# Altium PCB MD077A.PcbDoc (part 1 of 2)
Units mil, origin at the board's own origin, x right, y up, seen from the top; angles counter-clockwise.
Board outline 2838.2 x 1916.85 mil, 4 copper layers (Top Layer, Signal Layer 1, Signal Layer 2, Bottom Layer), stack 61.2 mil thick; 81 components, 30 nets, 187 pads, 201 vias.
Unrouted connection lines stored in the file: 7.
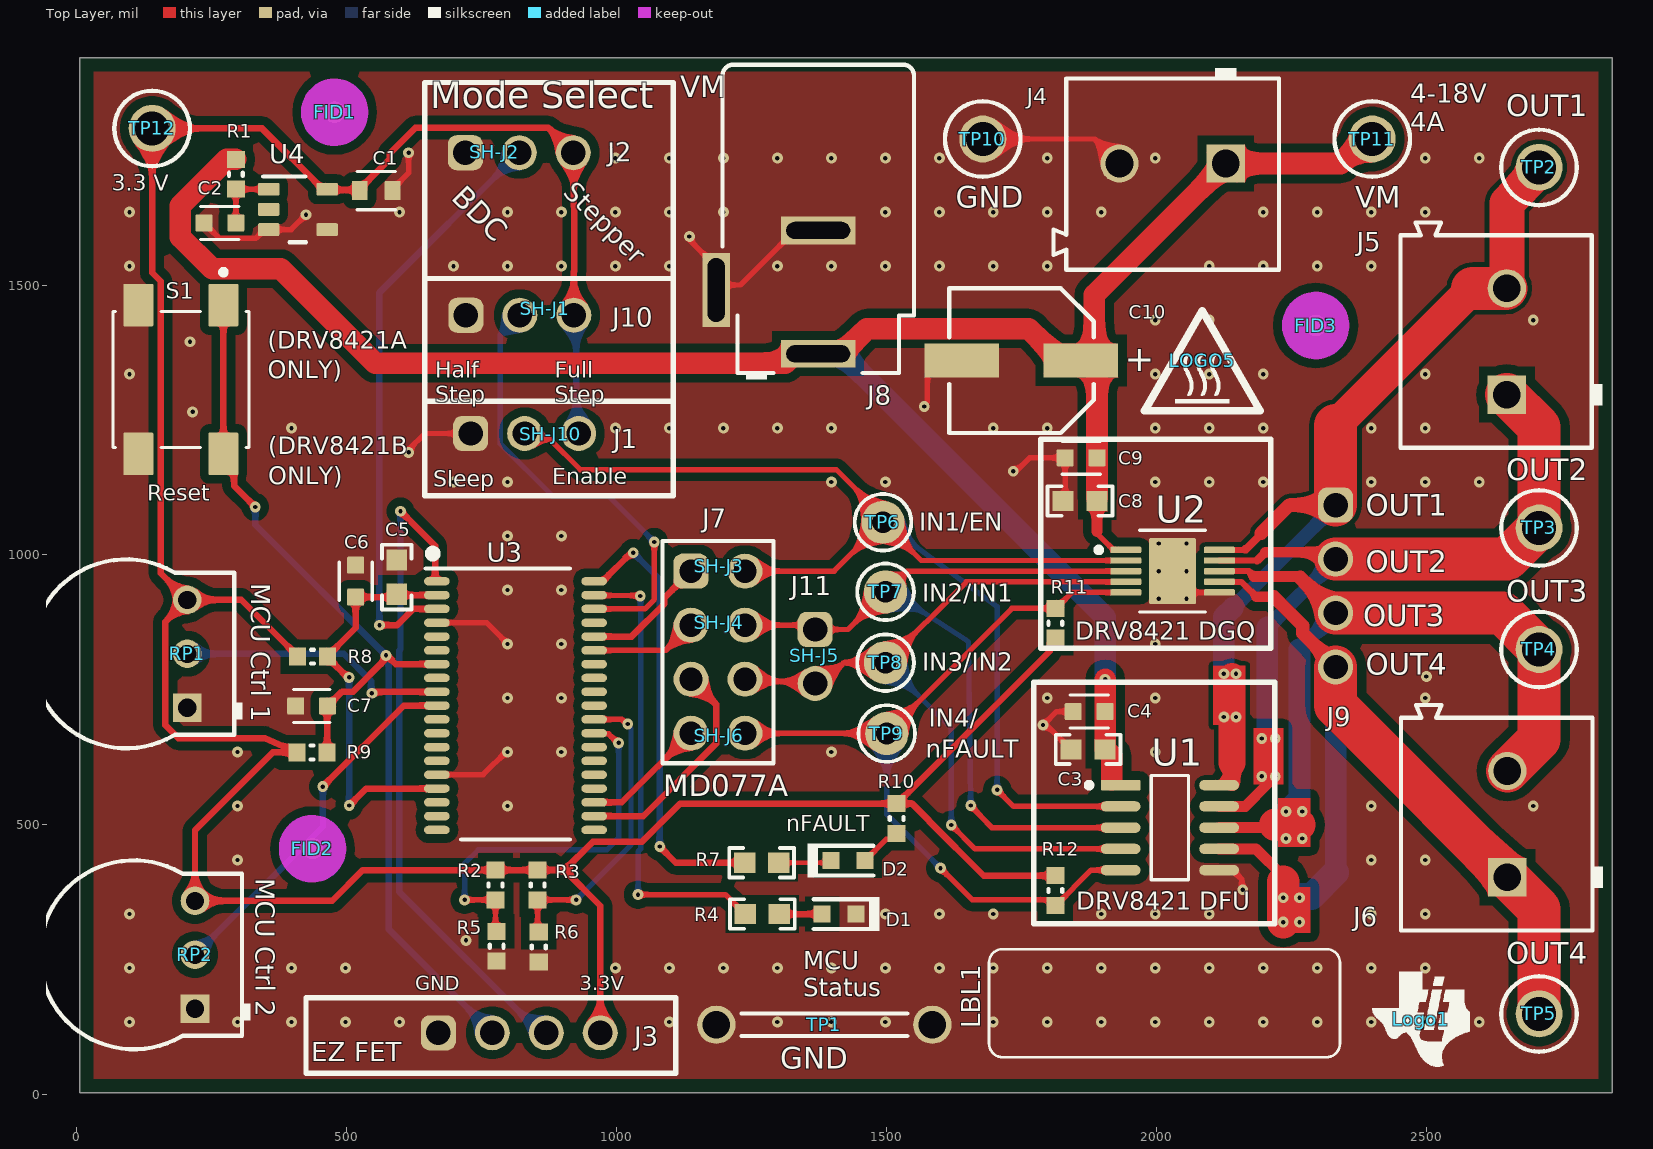
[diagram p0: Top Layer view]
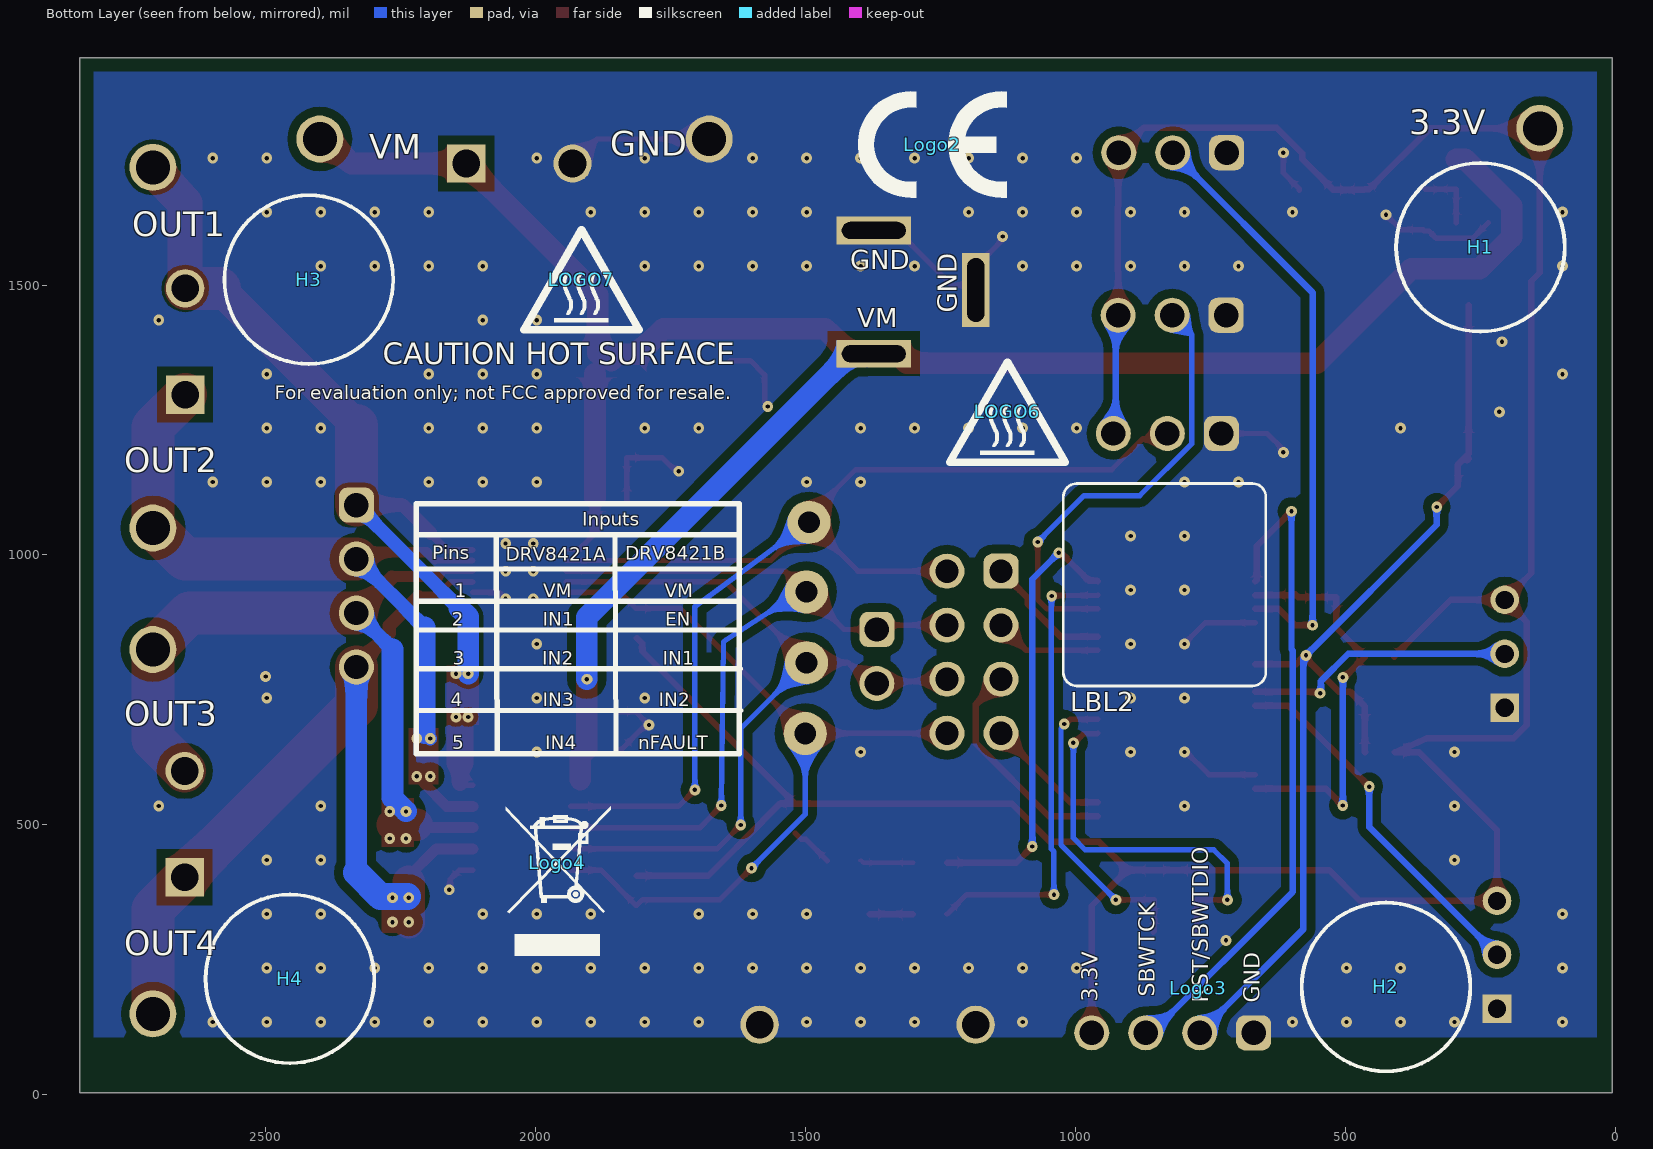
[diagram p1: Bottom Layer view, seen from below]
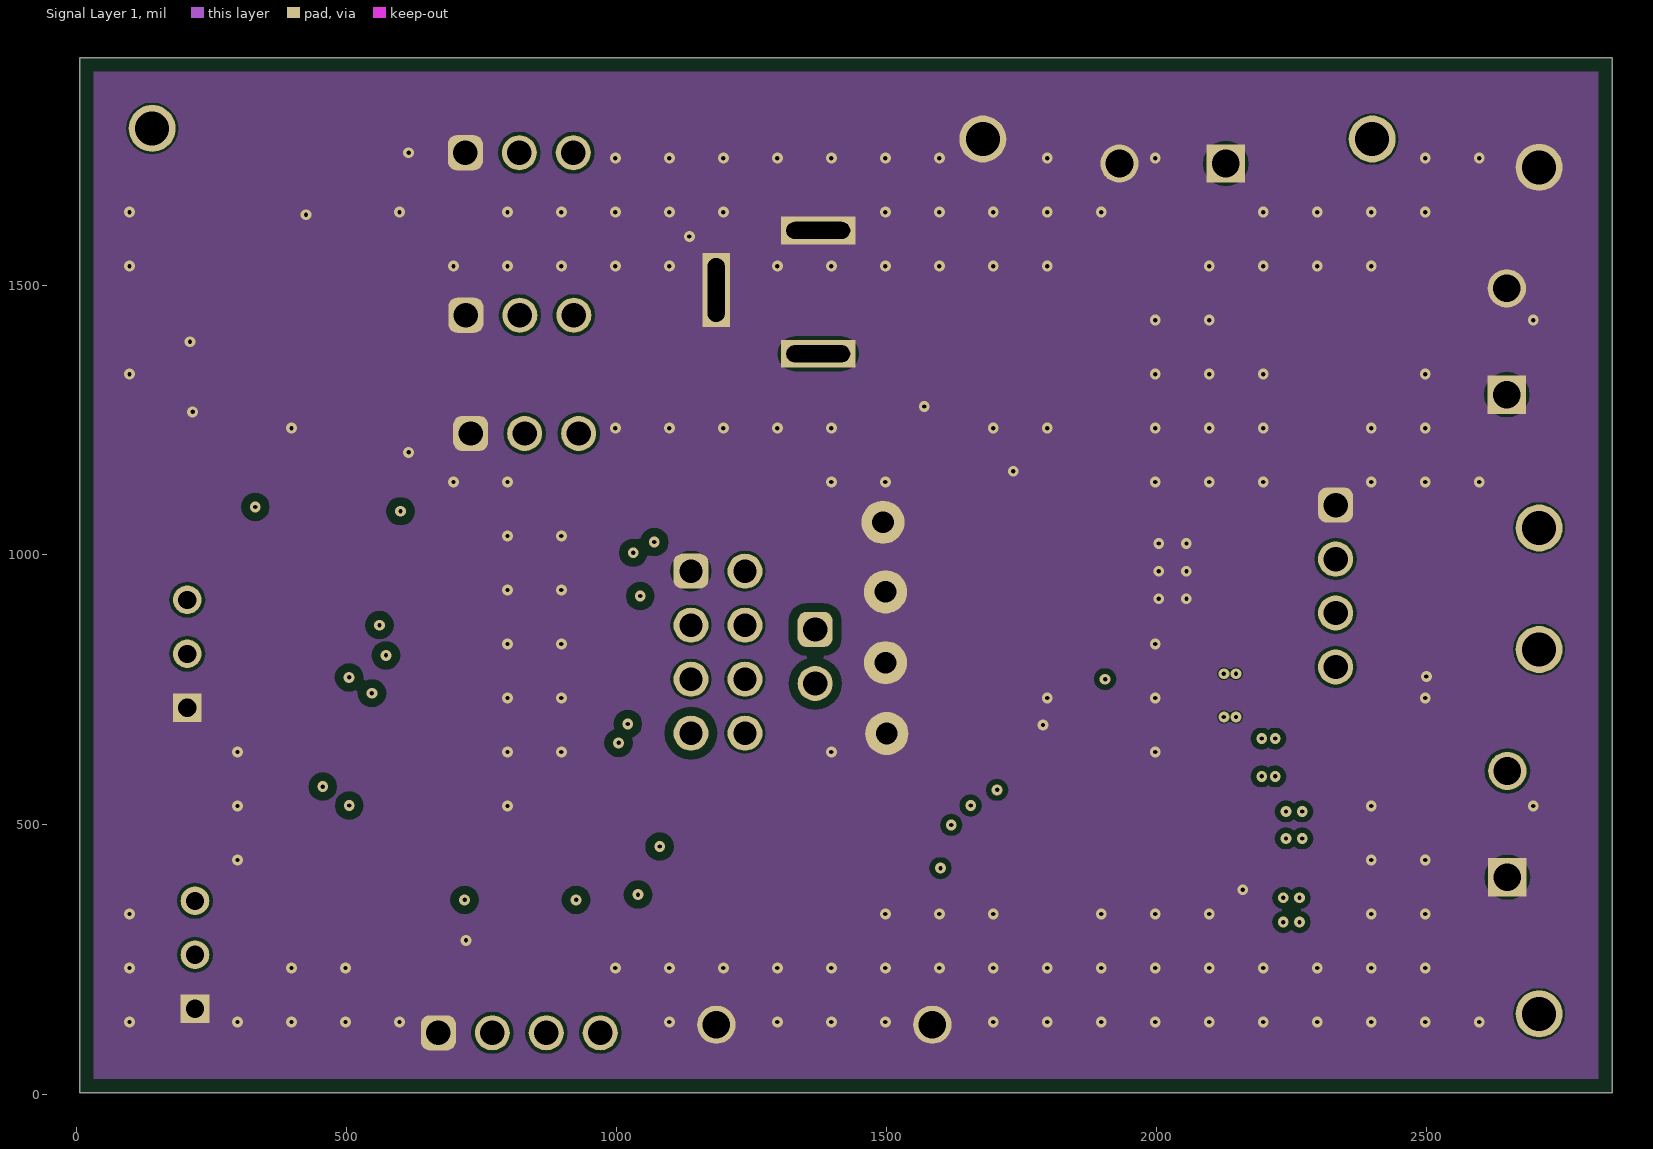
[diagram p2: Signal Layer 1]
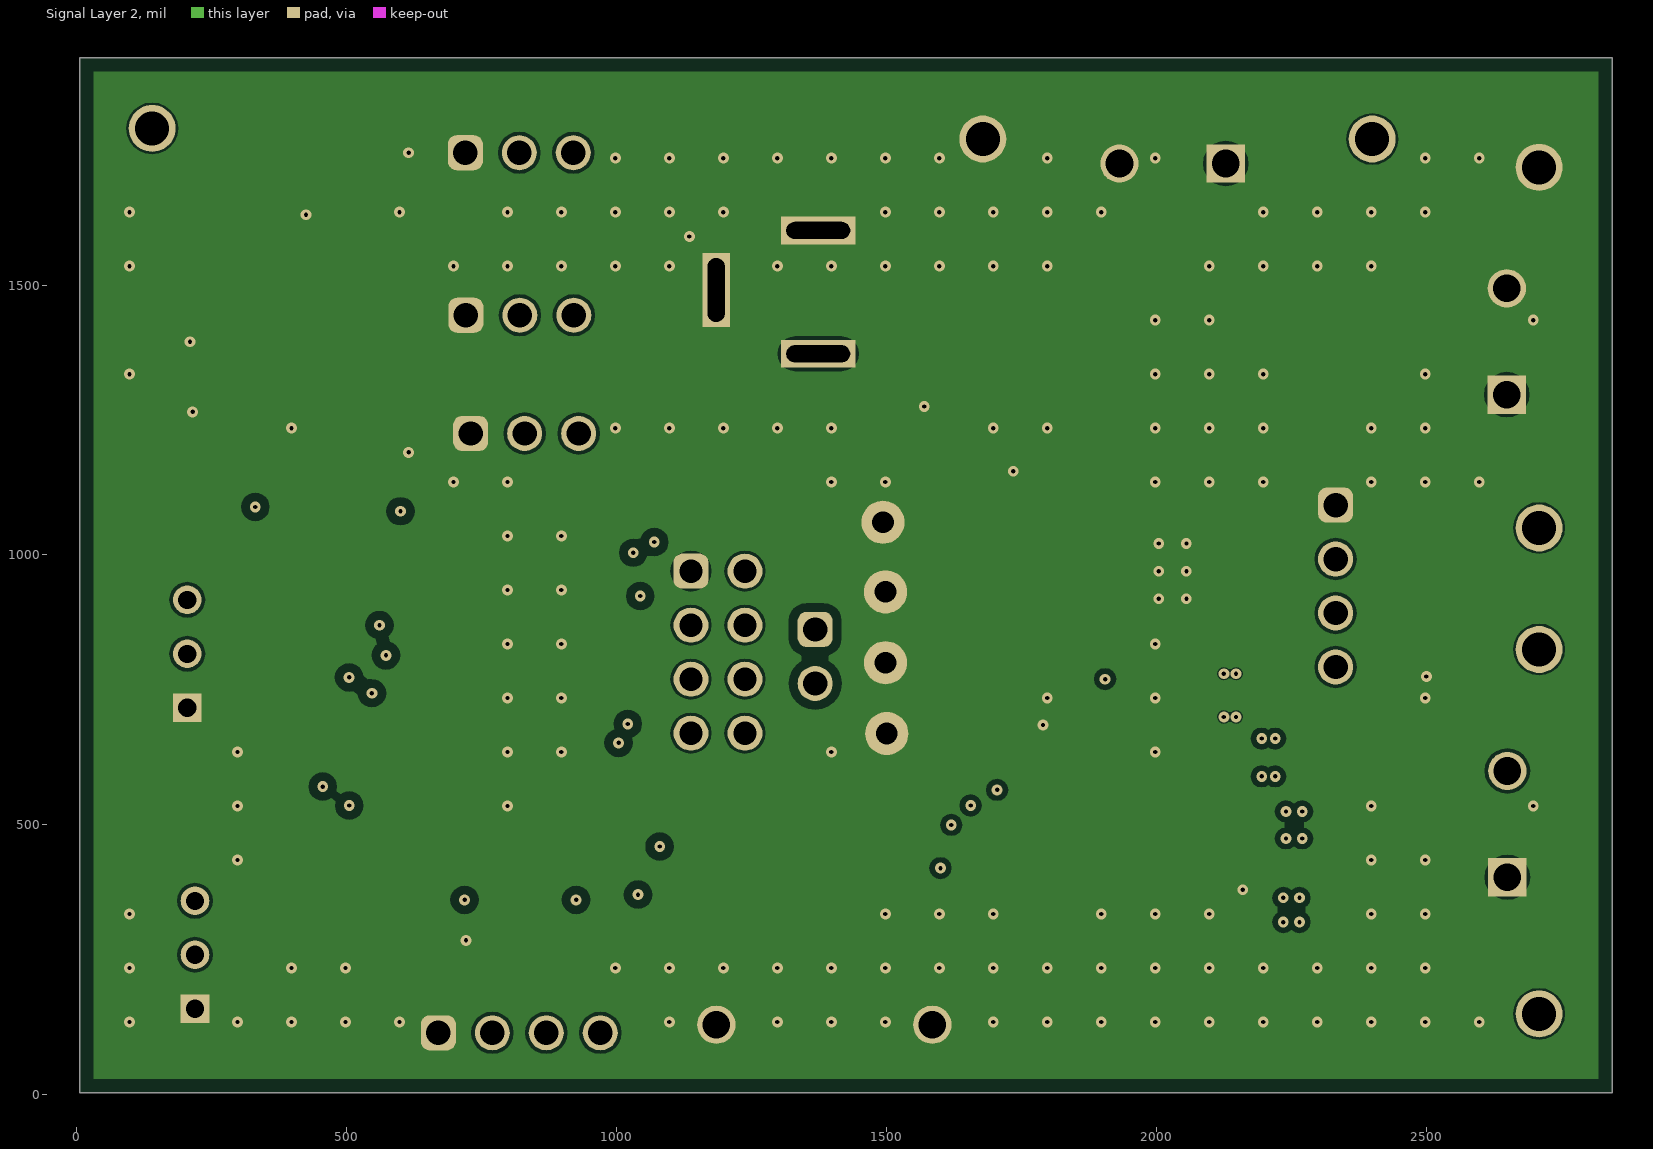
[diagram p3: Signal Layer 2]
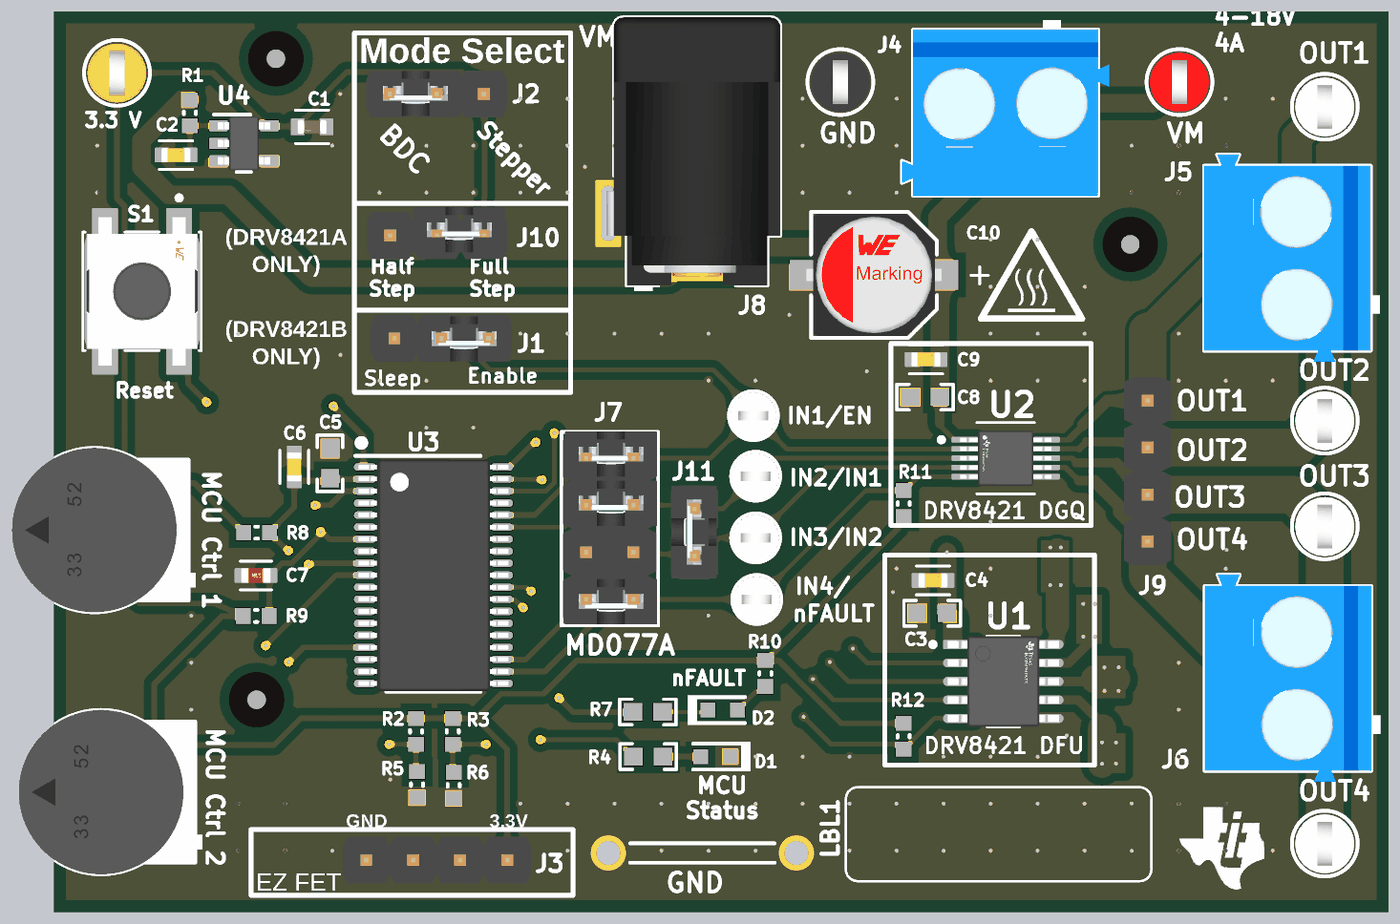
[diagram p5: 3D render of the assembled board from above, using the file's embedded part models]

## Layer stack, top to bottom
Top Solder: solder mask 0.4, Solder Resist, Dk 3.5
Top Layer: signal copper 2.8
Dielectric 1: prepreg 11.4, FR4 370, Dk 4.2
Signal Layer 1: signal copper 1.4
Dielectric 2: core 30, FR4 370, Dk 4.2
Signal Layer 2: signal copper 1.4
Dielectric 3: prepreg 11.4, FR4 370, Dk 4.2
Bottom Layer: signal copper 2.8
Bottom Solder: solder mask 0.4, Solder Resist, Dk 3.5

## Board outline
6,1920.85 6,4 2844.2,4 2844.2,1920.85

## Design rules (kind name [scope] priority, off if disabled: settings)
AcuteAngle [All] p1: minimum=4.50000000000000E+0001 checktracksonly=FALSE
AssemblyTestPointUsage [All] p1: valid=2
BoardOutlineClearance BoardOutlineClearance_MountingHoles [OnCopper and InComponentClass('Mounting Holes')] p1: gap=39.37 ignorepadtopadclearanceinfootprint=FALSE
BoardOutlineClearance BoardOutlineClearance_Poly [OnCopper and IsPoly] p2: gap=25 ignorepadtopadclearanceinfootprint=FALSE
BoardOutlineClearance BoardOutlineClearance_Region [OnCopper and IsRegion] p3: gap=25 ignorepadtopadclearanceinfootprint=FALSE
BoardOutlineClearance [OnCopper and Not InComponentClass('Logo') and not InComponentClass('FiducialMark') and not InRegion(1000,500,4000,800) and not InPoly] p4: gap=75 ignorepadtopadclearanceinfootprint=FALSE
Clearance Clearance_18 [InNet('OUT1')] p1: gap=8 ignorepadtopadclearanceinfootprint=TRUE
Clearance Clearance_Keepouts [((IsTrack Or IsArc) And Not InPoly) And IsFree and IsKeepOut vs ((IsTrack Or IsArc) And Not InPoly) And IsFree and IsKeepOut] p2: gap=0 ignorepadtopadclearanceinfootprint=FALSE
Clearance Clearance_Poly [InPolygon] p3: gap=16 ignorepadtopadclearanceinfootprint=TRUE
Clearance Clearance_FiducialMark [IsKeepOut and InComponentClass('FiducialMark') vs IsPad and InComponentClass('FiducialMark')] p4: gap=0 ignorepadtopadclearanceinfootprint=FALSE
Clearance [All] p5: gap=7.87 ignorepadtopadclearanceinfootprint=TRUE
ComponentClearance ComponentClearance_MountingHoles_FiducialMarks [InComponentClass('Mounting Holes') vs InComponentClass('FiducialMark')] p1: gap=50 collisioncheckmode=3 verticalgap=10 showdistances=FALSE
ComponentClearance ComponentClearance_Shunt [InComponentClass('Shunt')] p2: gap=0 collisioncheckmode=3 verticalgap=0 showdistances=FALSE
ComponentClearance ComponentClearance_Logo [InComponentClass('Logo')] p3: gap=50 collisioncheckmode=3 verticalgap=10 showdistances=FALSE
ComponentClearance ComponentClearance_ScrewToNut [(HasFootprint('NY PMS 440 0025 PH')) vs (HasFootprint('Keystone_1902C'))] p4: gap=5 collisioncheckmode=3 verticalgap=10 showdistances=FALSE
ComponentClearance ComponentClearance_MountingHoles [InComponentClass('Mounting Holes')] p5: gap=250 collisioncheckmode=3 verticalgap=100000 showdistances=FALSE
ComponentClearance ComponentClearance_SmallPassives [HasFootprint('0201*') or HasFootprint('0402*') or HasFootprint('0508') or HasFootprint('0603*') or HasFootprint('0612') or HasFootprint('0805*') or HasFootprint('0815*') or HasFootprint('0830*') or HasFootprint('1206*') or HasFootprint('1210*') or HasFootprint('1808*') or HasFootprint('1812*') or HasFootprint('1825*') or HasFootprint('2010*') or HasFootprint('2220*') or HasFootprint('2225*') or HasFootprint('2512*') or HasFootprint('2728*') or HasFootprint('3518*') vs HasFootprint('0201*') or HasFootprint('0402*') or HasFootprint('0508') or HasFootprint('0603*') or HasFootprint('0612') or HasFootprint('0805*') or HasFootprint('0815*') or HasFootprint('0830*') or HasFootprint('1206*') or HasFootprint('1210*') or HasFootprint('1808*') or HasFootprint('1812*') or HasFootprint('1825*') or HasFootprint('2010*') or HasFootprint('2220*') or HasFootprint('2225*') or HasFootprint('2512*') or HasFootprint('2728*') or HasFootprint('3518*')] p6: gap=14.96 collisioncheckmode=3 verticalgap=10 showdistances=FALSE
ComponentClearance ComponentClearance_THtoSMT [IsThruComponent vs IsSMTComponent] p7: gap=40 collisioncheckmode=3 verticalgap=30 showdistances=FALSE
ComponentClearance ComponentClearance_THtoTH [IsThruComponent vs IsThruComponent] p8: gap=30 collisioncheckmode=3 verticalgap=30 showdistances=FALSE
ComponentClearance [All] p9: gap=30 collisioncheckmode=3 verticalgap=10 showdistances=FALSE
DiffPairsRouting [All] p1: maxlimit=100 minlimit=10 mostfreqgap=10 toplayer_minwidth=6.3 toplayer_maxwidth=15 toplayer_prefwidth=10 midlayer1_minwidth=15 midlayer1_maxwidth=15 midlayer1_prefwidth=15 midlayer2_minwidth=15 midlayer2_maxwidth=15 midlayer2_prefwidth=15 bottomlayer_minwidth=6.3 bottomlayer_maxwidth=15 bottomlayer_prefwidth=10 maxuncoupledlength=1000
FabricationTestPointUsage TestPointUsage [All] p1: valid=2 allowmultiple=FALSE
FabricationTestpoint Testpoint [All] p1: side=3 testpointundercomponent=TRUE minsize=40 maxsize=100 preferedsize=60 minholesize=0 maxholesize=40 preferedholesize=32 testpointgrid=1 allowsidetop=TRUE allowsidebottom=TRUE usegrid=TRUE gridtolerance=0.01
FanoutControl Fanout_LCC [IsLCC] p1: bgadir=Out bgaviamode=Centered fanoutstyle=Auto fanoutdirection=Alternating viagrid=1 // Fanout_LCC (Default Rule)
FanoutControl Fanout_BGA [IsBGA] p2: bgadir=Out bgaviamode=Centered fanoutstyle=Auto fanoutdirection=Alternating viagrid=1 // Fanout_BGA (Default Rule)
FanoutControl Fanout_Default [All] p4: bgadir=Out bgaviamode=Centered fanoutstyle=Auto fanoutdirection=Alternating viagrid=1 // Fanout_Default (Default Rule)
FanoutControl Fanout_Small [(CompPinCount < 5)] p5: bgadir=Out bgaviamode=Centered fanoutstyle=Auto fanoutdirection=OutThenIn viagrid=1 // Fanout_Small (Default Rule)
HoleSize [All] p1: absolutevalues=TRUE maxlimit=251 minlimit=7.87 maxpercent=80.000 minpercent=20.000
HoleToHoleClearance [All] p1: gap=12 allowstackedmicrovias=TRUE
MinimumAnnularRing MinimumAnnularRing_ThermalPadVias [IsVia and InAnyComponent] p1: minimumring=5.91
MinimumAnnularRing [All] p2: minimumring=7.87
MinimumSolderMaskSliver MinimumSolderMaskSliver_Logo [InComponentClass('Logo') vs InComponentClass('Logo')] p1: minsoldermaskwidth=0.7
MinimumSolderMaskSliver [All] p2: minsoldermaskwidth=3.94
PlaneConnect [All] p1: planeconnectstyle=Direct reliefexpansion=10 reliefentries=4 reliefconductorwidth=10 reliefairgap=10
PolygonConnect PolygonConnect_94 [All vs IsNamedPolygon('BOTTOM_LAYER_GND_P203')] p1: thpad.connectstyle=Direct thpad.reliefconductorwidth=10 thpad.reliefentries=4 thpad.polygonreliefangle="90 Angle" thpad.airgapwidth=10 smdpad.connectstyle=Direct smdpad.reliefconductorwidth=10 smdpad.reliefentries=4 smdpad.polygonreliefangle="90 Angle" smdpad.airgapwidth=10 via.connectstyle=Relief via.reliefconductorwidth=10 via.reliefentries=4 via.polygonreliefangle="90 Angle" via.airgapwidth=10
PolygonConnect PolygonConnect_93 [All vs IsNamedPolygon('SIGNAL_LAYER_2_EZFET_VBUS_P136')] p2: thpad.connectstyle=Direct thpad.reliefconductorwidth=10 thpad.reliefentries=4 thpad.polygonreliefangle="90 Angle" thpad.airgapwidth=10 smdpad.connectstyle=Direct smdpad.reliefconductorwidth=10 smdpad.reliefentries=4 smdpad.polygonreliefangle="90 Angle" smdpad.airgapwidth=10 via.connectstyle=Relief via.reliefconductorwidth=10 via.reliefentries=4 via.polygonreliefangle="90 Angle" via.airgapwidth=10
PolygonConnect PolygonConnect_92 [All vs IsNamedPolygon('TOP_LAYER_VM_P244')] p3: thpad.connectstyle=Direct thpad.reliefconductorwidth=10 thpad.reliefentries=4 thpad.polygonreliefangle="90 Angle" thpad.airgapwidth=10 smdpad.connectstyle=Direct smdpad.reliefconductorwidth=10 smdpad.reliefentries=4 smdpad.polygonreliefangle="90 Angle" smdpad.airgapwidth=10 via.connectstyle=Relief via.reliefconductorwidth=10 via.reliefentries=4 via.polygonreliefangle="90 Angle" via.airgapwidth=10
PolygonConnect PolygonConnect_91 [All vs IsNamedPolygon('TOP_LAYER_BOUT2_P242')] p4: thpad.connectstyle=Direct thpad.reliefconductorwidth=10 thpad.reliefentries=4 thpad.polygonreliefangle="90 Angle" thpad.airgapwidth=10 smdpad.connectstyle=Direct smdpad.reliefconductorwidth=10 smdpad.reliefentries=4 smdpad.polygonreliefangle="90 Angle" smdpad.airgapwidth=10 via.connectstyle=Relief via.reliefconductorwidth=10 via.reliefentries=4 via.polygonreliefangle="90 Angle" via.airgapwidth=10
PolygonConnect PolygonConnect_90 [All vs IsNamedPolygon('TOP_LAYER_VM_P239')] p5: thpad.connectstyle=Direct thpad.reliefconductorwidth=10 thpad.reliefentries=4 thpad.polygonreliefangle="90 Angle" thpad.airgapwidth=10 smdpad.connectstyle=Direct smdpad.reliefconductorwidth=10 smdpad.reliefentries=4 smdpad.polygonreliefangle="90 Angle" smdpad.airgapwidth=10 via.connectstyle=Relief via.reliefconductorwidth=10 via.reliefentries=4 via.polygonreliefangle="90 Angle" via.airgapwidth=10
PolygonConnect PolygonConnect_89 [All vs IsNamedPolygon('TOP_LAYER_BOUT1_P240')] p6: thpad.connectstyle=Direct thpad.reliefconductorwidth=10 thpad.reliefentries=4 thpad.polygonreliefangle="90 Angle" thpad.airgapwidth=10 smdpad.connectstyle=Direct smdpad.reliefconductorwidth=10 smdpad.reliefentries=4 smdpad.polygonreliefangle="90 Angle" smdpad.airgapwidth=10 via.connectstyle=Relief via.reliefconductorwidth=10 via.reliefentries=4 via.polygonreliefangle="90 Angle" via.airgapwidth=10
PolygonConnect PolygonConnect_88 [All vs IsNamedPolygon('BOTTOM_LAYER_VM_P080')] p7: thpad.connectstyle=Direct thpad.reliefconductorwidth=10 thpad.reliefentries=4 thpad.polygonreliefangle="90 Angle" thpad.airgapwidth=10 smdpad.connectstyle=Direct smdpad.reliefconductorwidth=10 smdpad.reliefentries=4 smdpad.polygonreliefangle="90 Angle" smdpad.airgapwidth=10 via.connectstyle=Relief via.reliefconductorwidth=10 via.reliefentries=4 via.polygonreliefangle="90 Angle" via.airgapwidth=10
PolygonConnect PolygonConnect_87 [All vs IsNamedPolygon('TOP_LAYER_VM_P125')] p8: connectstyle=Direct reliefconductorwidth=10 reliefentries=4 polygonreliefangle="90 Angle" airgapwidth=10
PolygonConnect PolygonConnect_86 [All vs IsNamedPolygon('BOTTOM_LAYER_VM_P080')] p9: connectstyle=Direct reliefconductorwidth=10 reliefentries=4 polygonreliefangle="90 Angle" airgapwidth=10
PolygonConnect PolygonConnect_85 [All vs IsNamedPolygon('BOTTOM_LAYER_OUT2_P211')] p10: connectstyle=Direct reliefconductorwidth=10 reliefentries=4 polygonreliefangle="90 Angle" airgapwidth=10
PolygonConnect PolygonConnect_84 [All vs IsNamedPolygon('BOTTOM_LAYER_OUT1_P205')] p11: connectstyle=Direct reliefconductorwidth=10 reliefentries=4 polygonreliefangle="90 Angle" airgapwidth=10
PolygonConnect PolygonConnect_83 [All vs IsNamedPolygon('BOTTOM_LAYER_OUT1_P205')] p12: connectstyle=Direct reliefconductorwidth=10 reliefentries=4 polygonreliefangle="90 Angle" airgapwidth=10
PolygonConnect PolygonConnect_82 [All vs IsNamedPolygon('BOTTOM_LAYER_GND_P204')] p13: connectstyle=Direct reliefconductorwidth=10 reliefentries=4 polygonreliefangle="90 Angle" airgapwidth=10
PolygonConnect PolygonConnect_81 [All vs IsNamedPolygon('TOP_LAYER_NONET_P237')] p14: connectstyle=Direct reliefconductorwidth=10 reliefentries=4 polygonreliefangle="90 Angle" airgapwidth=10
PolygonConnect PolygonConnect_80 [All vs IsNamedPolygon('TOP_LAYER_GND_P086')] p15: connectstyle=Direct reliefconductorwidth=10 reliefentries=4 polygonreliefangle="90 Angle" airgapwidth=10
PolygonConnect PolygonConnect_79 [All vs IsNamedPolygon('TOP_LAYER_VM_P229')] p16: connectstyle=Direct reliefconductorwidth=10 reliefentries=4 polygonreliefangle="90 Angle" airgapwidth=10
PolygonConnect PolygonConnect_78 [All vs IsNamedPolygon('TOP_LAYER_GND_P086')] p17: connectstyle=Direct reliefconductorwidth=10 reliefentries=4 polygonreliefangle="90 Angle" airgapwidth=10
PolygonConnect PolygonConnect_77 [All vs IsNamedPolygon('TOP_LAYER_OUT1_P221')] p18: connectstyle=Direct reliefconductorwidth=10 reliefentries=4 polygonreliefangle="90 Angle" airgapwidth=10
PolygonConnect PolygonConnect_76 [All vs IsNamedPolygon('TOP_LAYER_OUT2_P173')] p19: connectstyle=Direct reliefconductorwidth=10 reliefentries=4 polygonreliefangle="90 Angle" airgapwidth=10
PolygonConnect PolygonConnect_75 [All vs IsNamedPolygon('TOP_LAYER_OUT2_P173')] p20: connectstyle=Direct reliefconductorwidth=10 reliefentries=4 polygonreliefangle="90 Angle" airgapwidth=10
PolygonConnect PolygonConnect_74 [All vs IsNamedPolygon('TOP_LAYER_OUT2_P173')] p21: connectstyle=Direct reliefconductorwidth=10 reliefentries=4 polygonreliefangle="90 Angle" airgapwidth=10
PolygonConnect PolygonConnect_73 [All vs IsNamedPolygon('TOP_LAYER_OUT1_P221')] p22: connectstyle=Direct reliefconductorwidth=10 reliefentries=4 polygonreliefangle="90 Angle" airgapwidth=10
PolygonConnect PolygonConnect_72 [All vs IsNamedPolygon('TOP_LAYER_GND_P121')] p23: connectstyle=Direct reliefconductorwidth=10 reliefentries=4 polygonreliefangle="90 Angle" airgapwidth=10
PolygonConnect PolygonConnect_71 [All vs IsNamedPolygon('TOP_LAYER_OUT2_P173') Or  IsNamedPolygon('TOP_LAYER_OUT1_P129')] p24: connectstyle=Direct reliefconductorwidth=10 reliefentries=4 polygonreliefangle="90 Angle" airgapwidth=10
PolygonConnect PolygonConnect_70 [All vs IsNamedPolygon('TOP_LAYER_OUT2_P173')] p25: connectstyle=Direct reliefconductorwidth=10 reliefentries=4 polygonreliefangle="90 Angle" airgapwidth=10
PolygonConnect PolygonConnect_69 [All vs IsNamedPolygon('TOP_LAYER_OUT1_P129')] p26: connectstyle=Direct reliefconductorwidth=10 reliefentries=4 polygonreliefangle="90 Angle" airgapwidth=10
PolygonConnect PolygonConnect_68 [All vs IsNamedPolygon('TOP_LAYER_VM_P085')] p27: connectstyle=Direct reliefconductorwidth=10 reliefentries=4 polygonreliefangle="90 Angle" airgapwidth=10
PolygonConnect PolygonConnect_67 [All vs IsNamedPolygon('BOTTOM_LAYER_P_IN_P174')] p28: connectstyle=Direct reliefconductorwidth=10 reliefentries=4 polygonreliefangle="90 Angle" airgapwidth=10
PolygonConnect PolygonConnect_66 [All vs IsNamedPolygon('BOTTOM_LAYER_NETF1_2_P203')] p29: connectstyle=Direct reliefconductorwidth=10 reliefentries=4 polygonreliefangle="90 Angle" airgapwidth=10
PolygonConnect PolygonConnect_65 [All vs IsNamedPolygon('BOTTOM_LAYER_VBAT_P165')] p30: connectstyle=Direct reliefconductorwidth=10 reliefentries=4 polygonreliefangle="90 Angle" airgapwidth=10
PolygonConnect PolygonConnect_64 [All vs IsNamedPolygon('TOP_LAYER_VM_P167')] p31: connectstyle=Direct reliefconductorwidth=10 reliefentries=4 polygonreliefangle="90 Angle" airgapwidth=10
PolygonConnect PolygonConnect_63 [All vs IsNamedPolygon('TOP_LAYER_VM_P167')] p32: connectstyle=Direct reliefconductorwidth=10 reliefentries=4 polygonreliefangle="90 Angle" airgapwidth=10
PolygonConnect PolygonConnect_62 [All vs IsNamedPolygon('TOP_LAYER_VM_P171')] p33: connectstyle=Direct reliefconductorwidth=10 reliefentries=4 polygonreliefangle="90 Angle" airgapwidth=10
PolygonConnect PolygonConnect_61 [All vs IsNamedPolygon('SIGNAL_LAYER_2_GND_P199')] p34: connectstyle=Direct reliefconductorwidth=10 reliefentries=4 polygonreliefangle="90 Angle" airgapwidth=10
PolygonConnect PolygonConnect_60 [All vs IsNamedPolygon('SIGNAL_LAYER_2_NETF1_2_P196')] p35: connectstyle=Direct reliefconductorwidth=10 reliefentries=4 polygonreliefangle="90 Angle" airgapwidth=10
PolygonConnect PolygonConnect_59 [All vs IsNamedPolygon('SIGNAL_LAYER_2_VBAT_P197')] p36: connectstyle=Direct reliefconductorwidth=10 reliefentries=4 polygonreliefangle="90 Angle" airgapwidth=10
PolygonConnect PolygonConnect_58 [All vs IsNamedPolygon('SIGNAL_LAYER_2_P_IN_P198')] p37: connectstyle=Direct reliefconductorwidth=10 reliefentries=4 polygonreliefangle="90 Angle" airgapwidth=10
PolygonConnect PolygonConnect_57 [All vs IsNamedPolygon('SIGNAL_LAYER_2_3V3_P194')] p38: connectstyle=Direct reliefconductorwidth=10 reliefentries=4 polygonreliefangle="90 Angle" airgapwidth=10
PolygonConnect PolygonConnect_56 [All vs IsNamedPolygon('TOP_LAYER_NETF1_2_P207')] p39: connectstyle=Direct reliefconductorwidth=10 reliefentries=4 polygonreliefangle="90 Angle" airgapwidth=10
PolygonConnect PolygonConnect_55 [All vs IsNamedPolygon('TOP_LAYER_VBAT_P223')] p40: connectstyle=Direct reliefconductorwidth=10 reliefentries=4 polygonreliefangle="90 Angle" airgapwidth=10
PolygonConnect PolygonConnect_54 [All vs IsNamedPolygon('TOP_LAYER_P_IN_P227')] p41: connectstyle=Direct reliefconductorwidth=10 reliefentries=4 polygonreliefangle="90 Angle" airgapwidth=10
PolygonConnect PolygonConnect_53 [All vs IsNamedPolygon('TOP_LAYER_GND_P086')] p42: connectstyle=Direct reliefconductorwidth=10 reliefentries=4 polygonreliefangle="90 Angle" airgapwidth=10
PolygonConnect PolygonConnect_52 [All vs IsNamedPolygon('SIGNAL_LAYER_2_VM_P177') Or  IsNamedPolygon('SIGNAL_LAYER_2_VM_P179') Or  IsNamedPolygon('SIGNAL_LAYER_2_VM_P160') Or  IsNamedPolygon('SIGNAL_LAYER_2_VM_P175') Or  IsNamedPolygon('SIGNAL_LAYER_2_VM_P181')] p43: connectstyle=Direct reliefconductorwidth=10 reliefentries=4 polygonreliefangle="90 Angle" airgapwidth=10
PolygonConnect PolygonConnect_51 [All vs IsNamedPolygon('SIGNAL_LAYER_2_EZFET_VBUS_P136')] p44: connectstyle=Direct reliefconductorwidth=10 reliefentries=4 polygonreliefangle="90 Angle" airgapwidth=10
PolygonConnect PolygonConnect_50 [All vs IsNamedPolygon('SIGNAL_LAYER_2_EZFET_VCC_P132')] p45: connectstyle=Direct reliefconductorwidth=10 reliefentries=4 polygonreliefangle="90 Angle" airgapwidth=10
PolygonConnect PolygonConnect_49 [All vs IsNamedPolygon('SIGNAL_LAYER_2_MCU_3V3_P192')] p46: connectstyle=Direct reliefconductorwidth=10 reliefentries=4 polygonreliefangle="90 Angle" airgapwidth=10
PolygonConnect PolygonConnect_48 [All vs IsNamedPolygon('SIGNAL_LAYER_1_GND_P190')] p47: connectstyle=Direct reliefconductorwidth=10 reliefentries=4 polygonreliefangle="90 Angle" airgapwidth=10
PolygonConnect PolygonConnect_47 [All vs IsNamedPolygon('SIGNAL_LAYER_1_GND_P184')] p48: connectstyle=Direct reliefconductorwidth=10 reliefentries=4 polygonreliefangle="90 Angle" airgapwidth=10
PolygonConnect PolygonConnect_46 [All vs IsNamedPolygon('BOTTOM_LAYER_GND_P241')] p49: connectstyle=Direct reliefconductorwidth=10 reliefentries=4 polygonreliefangle="90 Angle" airgapwidth=10
PolygonConnect PolygonConnect_45 [All vs IsNamedPolygon('BOTTOM_LAYER_GND_P241')] p50: connectstyle=Direct reliefconductorwidth=10 reliefentries=4 polygonreliefangle="90 Angle" airgapwidth=10
PolygonConnect PolygonConnect_44 [All vs IsNamedPolygon('BOTTOM_LAYER_OUT2_P163')] p51: connectstyle=Direct reliefconductorwidth=10 reliefentries=4 polygonreliefangle="90 Angle" airgapwidth=10
PolygonConnect PolygonConnect_43 [All vs IsNamedPolygon('BOTTOM_LAYER_VM_P166')] p52: connectstyle=Direct reliefconductorwidth=10 reliefentries=4 polygonreliefangle="90 Angle" airgapwidth=10
PolygonConnect PolygonConnect_42 [All vs IsNamedPolygon('BOTTOM_LAYER_VM_P235')] p53: connectstyle=Direct reliefconductorwidth=10 reliefentries=4 polygonreliefangle="90 Angle" airgapwidth=10
PolygonConnect PolygonConnect_41 [All vs IsNamedPolygon('BOTTOM_LAYER_OUT1_P164')] p54: connectstyle=Direct reliefconductorwidth=10 reliefentries=4 polygonreliefangle="90 Angle" airgapwidth=10
PolygonConnect PolygonConnect_40 [All vs IsNamedPolygon('BOTTOM_LAYER_GND_P162')] p55: connectstyle=Direct reliefconductorwidth=10 reliefentries=4 polygonreliefangle="90 Angle" airgapwidth=10
PolygonConnect PolygonConnect_39 [All vs IsNamedPolygon('SIGNAL_LAYER_2_VM_P160')] p56: connectstyle=Direct reliefconductorwidth=10 reliefentries=4 polygonreliefangle="90 Angle" airgapwidth=10
PolygonConnect PolygonConnect_38 [All vs IsNamedPolygon('SIGNAL_LAYER_2_NONET_P138')] p57: connectstyle=Direct reliefconductorwidth=10 reliefentries=4 polygonreliefangle="90 Angle" airgapwidth=10
PolygonConnect PolygonConnect_37 [All vs IsNamedPolygon('SIGNAL_LAYER_1_VM_P146')] p58: connectstyle=Direct reliefconductorwidth=10 reliefentries=4 polygonreliefangle="90 Angle" airgapwidth=10
PolygonConnect PolygonConnect_36 [All vs IsNamedPolygon('SIGNAL_LAYER_2_GND_P156')] p59: connectstyle=Direct reliefconductorwidth=10 reliefentries=4 polygonreliefangle="90 Angle" airgapwidth=10
PolygonConnect PolygonConnect_35 [All vs IsNamedPolygon('BOTTOM_LAYER_EZFET_USB_SHIELD_P219')] p60: connectstyle=Direct reliefconductorwidth=10 reliefentries=4 polygonreliefangle="90 Angle" airgapwidth=10
PolygonConnect PolygonConnect_34 [All vs IsNamedPolygon('SIGNAL_LAYER_1_VM_P144')] p61: connectstyle=Direct reliefconductorwidth=10 reliefentries=4 polygonreliefangle="90 Angle" airgapwidth=10
PolygonConnect PolygonConnect_33 [All vs IsNamedPolygon('SIGNAL_LAYER_1_VM_P148') Or  IsNamedPolygon('SIGNAL_LAYER_1_VM_P148')] p62: connectstyle=Direct reliefconductorwidth=10 reliefentries=4 polygonreliefangle="90 Angle" airgapwidth=10
PolygonConnect PolygonConnect_32 [All vs IsNamedPolygon('SIGNAL_LAYER_1_GND_P154')] p63: connectstyle=Direct reliefconductorwidth=10 reliefentries=4 polygonreliefangle="90 Angle" airgapwidth=10
PolygonConnect PolygonConnect_31 [All vs IsNamedPolygon('SIGNAL_LAYER_2_NONET_P138')] p64: connectstyle=Direct reliefconductorwidth=10 reliefentries=4 polygonreliefangle="90 Angle" airgapwidth=10
PolygonConnect PolygonConnect_30 [All vs IsNamedPolygon('SIGNAL_LAYER_2_GND_P082')] p65: connectstyle=Direct reliefconductorwidth=10 reliefentries=4 polygonreliefangle="90 Angle" airgapwidth=10
PolygonConnect PolygonConnect_29 [All vs IsNamedPolygon('TOP_LAYER_GND_P076')] p66: connectstyle=Direct reliefconductorwidth=10 reliefentries=4 polygonreliefangle="90 Angle" airgapwidth=10
PolygonConnect PolygonConnect_28 [All vs IsNamedPolygon('TOP_LAYER_GND_P087')] p67: connectstyle=Direct reliefconductorwidth=10 reliefentries=4 polygonreliefangle="90 Angle" airgapwidth=10
PolygonConnect PolygonConnect_27 [All vs IsNamedPolygon('TOP_LAYER_VM_P127') Or  IsNamedPolygon('TOP_LAYER_VM_P085')] p68: connectstyle=Direct reliefconductorwidth=10 reliefentries=4 polygonreliefangle="90 Angle" airgapwidth=10
PolygonConnect PolygonConnect_26 [All vs IsNamedPolygon('TOP_LAYER_GND_P117')] p69: connectstyle=Direct reliefconductorwidth=10 reliefentries=4 polygonreliefangle="90 Angle" airgapwidth=10
PolygonConnect PolygonConnect_25 [All vs IsNamedPolygon('TOP_LAYER_OUT1_P129') Or  IsNamedPolygon('TOP_LAYER_OUT2_P173')] p70: connectstyle=Direct reliefconductorwidth=10 reliefentries=4 polygonreliefangle="90 Angle" airgapwidth=10
PolygonConnect PolygonConnect_24 [All vs IsNamedPolygon('SIGNAL_LAYER_2_NONET_P113')] p71: connectstyle=Direct reliefconductorwidth=10 reliefentries=4 polygonreliefangle="90 Angle" airgapwidth=10
PolygonConnect PolygonConnect_23 [All vs IsNamedPolygon('BOTTOM_LAYER_NONET_P115')] p72: connectstyle=Direct reliefconductorwidth=10 reliefentries=4 polygonreliefangle="90 Angle" airgapwidth=10
PolygonConnect PolygonConnect_22 [All vs IsNamedPolygon('SIGNAL_LAYER_1_NONET_P111')] p73: connectstyle=Direct reliefconductorwidth=10 reliefentries=4 polygonreliefangle="90 Angle" airgapwidth=10
PolygonConnect PolygonConnect_21 [All vs IsNamedPolygon('TOP_LAYER_NONET_P083')] p74: connectstyle=Direct reliefconductorwidth=10 reliefentries=4 polygonreliefangle="90 Angle" airgapwidth=10
PolygonConnect PolygonConnect_20 [All vs IsNamedPolygon('TOP_LAYER_NONET_P105')] p75: connectstyle=Direct reliefconductorwidth=10 reliefentries=4 polygonreliefangle="90 Angle" airgapwidth=10
PolygonConnect PolygonConnect_19 [All vs IsNamedPolygon('TOP_LAYER_OUT2_P107')] p76: connectstyle=Direct reliefconductorwidth=10 reliefentries=4 polygonreliefangle="90 Angle" airgapwidth=10
PolygonConnect PolygonConnect_18 [All vs IsNamedPolygon('TOP_LAYER_NONET_P101')] p77: connectstyle=Direct reliefconductorwidth=10 reliefentries=4 polygonreliefangle="90 Angle" airgapwidth=10
PolygonConnect PolygonConnect_17 [All vs IsNamedPolygon('TOP_LAYER_OUT1_P103')] p78: connectstyle=Direct reliefconductorwidth=10 reliefentries=4 polygonreliefangle="90 Angle" airgapwidth=10
PolygonConnect PolygonConnect_16 [All vs IsNamedPolygon('TOP_LAYER_OUT1_P000')] p79: connectstyle=Direct reliefconductorwidth=10 reliefentries=4 polygonreliefangle="90 Angle" airgapwidth=10
PolygonConnect PolygonConnect_15 [All vs IsNamedPolygon('TOP_LAYER_NONET_P093')] p80: connectstyle=Direct reliefconductorwidth=10 reliefentries=4 polygonreliefangle="90 Angle" airgapwidth=10
PolygonConnect PolygonConnect_14 [All vs IsNamedPolygon('TOP_LAYER_OUT2_P099')] p81: connectstyle=Direct reliefconductorwidth=10 reliefentries=4 polygonreliefangle="90 Angle" airgapwidth=10
PolygonConnect PolygonConnect_13 [All vs IsNamedPolygon('TOP_LAYER_OUT1_P000')] p82: connectstyle=Direct reliefconductorwidth=10 reliefentries=4 polygonreliefangle="90 Angle" airgapwidth=10
PolygonConnect PolygonConnect_12 [All vs IsNamedPolygon('BOTTOM_LAYER_NONET_P079') Or  IsNamedPolygon('SIGNAL_LAYER_2_NONET_P078') Or  IsNamedPolygon('SIGNAL_LAYER_1_NONET_P077') Or  IsNamedPolygon('TOP_LAYER_NONET_P083') Or  IsNamedPolygon('BOTTOM_LAYER_NONET_P072') Or  IsNamedPolygon('SIGNAL_LAYER_2_NONET_P070') Or  IsNamedPolygon('SIGNAL_LAYER_1_NONET_P059') Or  IsNamedPolygon('TOP_LAYER_OUT2_P058') Or  IsNamedPolygon('BOTTOM_LAYER_NONET_P056') Or  IsNamedPolygon('SIGNAL_LAYER_2_NONET_P054') Or  IsNamedPolygon('SIGNAL_LAYER_1_NONET_P052') Or  IsNamedPolygon('TOP_LAYER_OUT1_P050') Or  IsNamedPolygon('BOTTOM_LAYER_VM_P044') Or  IsNamedPolygon('SIGNAL_LAYER_2_VM_P042') Or  IsNamedPolygon('SIGNAL_LAYER_1_VM_P040') Or  IsNamedPolygon('TOP_LAYER_VM_P038') Or  IsNamedPolygon('BOTTOM_LAYER_VM_P036') Or  IsNamedPolygon('SIGNAL_LAYER_2_VM_P018') Or  IsNamedPolygon('SIGNAL_LAYER_1_VM_P016') Or  IsNamedPolygon('TOP_LAYER_VM_P002')] p83: connectstyle=Direct reliefconductorwidth=10 reliefentries=4 polygonreliefangle="90 Angle" airgapwidth=10
PolygonConnect PolygonConnect_11 [All vs IsNamedPolygon('TOP_LAYER_NONET_P089') Or  IsNamedPolygon('TOP_LAYER_NONET_P090')] p84: connectstyle=Direct reliefconductorwidth=10 reliefentries=4 polygonreliefangle="90 Angle" airgapwidth=10
PolygonConnect PolygonConnect_10 [All vs IsNamedPolygon('BOTTOM_LAYER_EZFET_USB_SHIELD_P002') Or  IsNamedPolygon('TOP_LAYER_EZFET_USB_SHIELD_P201') Or  IsNamedPolygon('SIGNAL_LAYER_2_EZFET_VBUS_P018') Or  IsNamedPolygon('SIGNAL_LAYER_2_EZFET_VCC_P016')] p85: connectstyle=Direct reliefconductorwidth=10 reliefentries=4 polygonreliefangle="90 Angle" airgapwidth=10
PolygonConnect PolygonConnect_9 [All vs IsNamedPolygon('TOP_LAYER_VM_P123') Or  IsNamedPolygon('TOP_LAYER_VM_P123') Or  IsNamedPolygon('TOP_LAYER_VM_P123')] p86: connectstyle=Direct reliefconductorwidth=10 reliefentries=4 polygonreliefangle="90 Angle" airgapwidth=10
PolygonConnect PolygonConnect_8 [All vs IsNamedPolygon('TOP_LAYER_NONET_P072')] p87: connectstyle=Direct reliefconductorwidth=10 reliefentries=4 polygonreliefangle="90 Angle" airgapwidth=10
PolygonConnect PolygonConnect_7 [All vs IsNamedPolygon('TOP_LAYER_NONET_P072')] p88: connectstyle=Direct reliefconductorwidth=10 reliefentries=4 polygonreliefangle="90 Angle" airgapwidth=10
PolygonConnect PolygonConnect_6 [All vs IsNamedPolygon('TOP_LAYER_VM_P042')] p89: connectstyle=Direct reliefconductorwidth=10 reliefentries=4 polygonreliefangle="90 Angle" airgapwidth=10
PolygonConnect PolygonConnect_5 [All vs IsNamedPolygon('TOP_LAYER_VM_P044')] p90: connectstyle=Direct reliefconductorwidth=10 reliefentries=4 polygonreliefangle="90 Angle" airgapwidth=10
PolygonConnect PolygonConnect_4 [All vs IsNamedPolygon('TOP_LAYER_VM_P046')] p91: connectstyle=Direct reliefconductorwidth=10 reliefentries=4 polygonreliefangle="90 Angle" airgapwidth=10
PolygonConnect PolygonConnect_3 [All vs IsNamedPolygon('TOP_LAYER_GND_P036') Or  IsNamedPolygon('TOP_LAYER_OUT2_P040') Or  IsNamedPolygon('TOP_LAYER_OUT1_P038')] p92: connectstyle=Direct reliefconductorwidth=10 reliefentries=4 polygonreliefangle="90 Angle" airgapwidth=10
PolygonConnect PolygonConnect_2 [InNet('EZFET_VBUS') vs IsNamedPolygon('TOP_LAYER_EZFET_VBUS_P008')] p93: connectstyle=Direct reliefconductorwidth=10 reliefentries=4 polygonreliefangle="90 Angle" airgapwidth=10
PolygonConnect PolygonConnect_1 [InNetClass('Power-Net') vs IsNamedPolygon('TOP_LAYER_EZFET_USB_SHIELD_P201')] p94: connectstyle=Direct reliefconductorwidth=10 reliefentries=4 polygonreliefangle="90 Angle" airgapwidth=10
PolygonConnect [All] p95: connectstyle=Direct reliefconductorwidth=10 reliefentries=4 polygonreliefangle="90 Angle" airgapwidth=10
RoutingVias ThermalPadVias [IsVia and InAnyComponent] p1: holewidth=7.87 width=19.68 viastyle="Through Hole" minholewidth=7.87 minwidth=19.68 maxholewidth=12.99 maxwidth=23.62
RoutingVias [All] p2: holewidth=16 width=34 viastyle="Through Hole" minholewidth=7.87 minwidth=26 maxholewidth=40 maxwidth=65
SilkToBoardRegionClearance [Not ((IsComment or IsDesignator) And (Hide <> 'False')) and not InRegion(1000,500,4000,800)] p1:
SilkToSilkClearance SilkToSilkClearance_Pb-FreeLogo [(HasFootprint('Pb-Free_Overlay_Medium') OR HasFootprint('Pb-Free_Overlay_Small')) vs (HasFootprint('Pb-Free_Overlay_Medium') OR HasFootprint('Pb-Free_Overlay_Small'))] p1: silktosilkclearance=0
SilkToSilkClearance [All] p2: silktosilkclearance=3.94
SilkToSolderMaskClearance SilkToComponentPadClearance [(IsPad or IsFill or IsRegion) and InAnycomponent] p1: minsilkscreentomaskgap=5 clearancetoexposedcopper=TRUE
SilkToSolderMaskClearance "Silk to Solder Mask Opening" [All] p2: minsilkscreentomaskgap=3.94 clearancetoexposedcopper=FALSE
SolderMaskExpansion [All] p1: expansion=1.97 istentingtop=FALSE
UnRoutedNet [All] p1: checkbadconnections=TRUE
Width [All] p1: maxlimit=120 minlimit=6 preferedwidth=8 checkconnectedcopper=TRUE
13 further rules are at their usual default settings.

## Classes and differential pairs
component class MD077A: C1 C2 C3 C4 C5 C6 C7 C8 C9 C10 D1 D2 J1 J2 J3 J4 J5 J6 J7 J8 J9 J10 J11 R1 R2 R3 R4 R5 R6 R7 R8 R9 R10 R11 R12 RP1 RP2 S1 SH-J1 SH-J2 SH-J3 SH-J4 SH-J5 SH-J6 SH-J10 TP1 TP2 TP3 TP4 TP5 TP6 TP7 TP8 TP9 TP10 TP11 TP12 U1 U2 U3 U4
component class FiducialMark: FID1 FID2 FID3
component class MD077A_Hardware: !PCB1 FID1 FID2 FID3 H1 H2 H3 H4 LBL1 LBL2 Logo1 Logo2 Logo3 Logo4 LOGO5 LOGO6 LOGO7 ZZ1 ZZ2 ZZ3 ZZ4
component class Shunt: SH-J1 SH-J2 SH-J3 SH-J4 SH-J5 SH-J6 SH-J10
component class Header: J1 J2 J3 J9 J10 J11
component class Logo: Logo1
component class AssemblyNote: ZZ1 ZZ2 ZZ3 ZZ4
component class Label: LBL1 LBL2

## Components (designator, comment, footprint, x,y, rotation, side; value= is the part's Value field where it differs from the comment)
C1 "GRM188R61E475KE15D" FP-GRM188R61E475KE15D_0603-MFG 555,1675 r180 top value=4.7µF
C2 "885012106031" FP-885012106031_0603-MFG 265.47,1615 r0 top value=10µF
C3 "885012206071" 0603 1873.5,640 r180 top value=0.1uF
C4 "885012106031" FP-885012106031_0603-MFG 1875.47,710 r0 top value=10µF
C5 "885012206071" 0603 593,959 r90 top value=0.1uF
C6 "885012106031" FP-885012106031_0603-MFG 517,951.53 r270 top value=10µF
C7 "885012006044" FP-885012006044_0603-MFG 435.47,720.32 r0 top value=1nF
C8 "885012206071" 0603 1858.5,1100 r180 top value=0.1uF
C9 "885012106031" FP-885012106031_0603-MFG 1860.47,1180 r0 top value=10µF
C10 "865080443007" WCAP-ASLI_D6.3H5.5 1750,1360 r0 top value=47uF
D1 "150060VS75000" WL-SMCW_GREEN 1412.5,335 r180 top value=Green
D2 "150060RS75000" WL-SMCW_RED 1428.5,434 r0 top value=Red
FID1 "Fiducial" Fiducial10-30 478,1820 r0 top
FID2 "Fiducial" Fiducial10-30 437,456 r90 top
FID3 "Fiducial" Fiducial10-30 2295,1425 r90 top
H1 "SJ61A1" Bumpon_SJ61A1 250,1570 r180 bottom
H2 "SJ61A1" Bumpon_SJ61A1 425,200 r180 bottom
H3 "SJ61A1" Bumpon_SJ61A1 2420,1510 r180 bottom
H4 "SJ61A1" Bumpon_SJ61A1 2455,215 r180 bottom
J1 "61300311121" WURTH_61300311121 830,1225 r0 top
J2 "61300311121" WURTH_61300311121 820,1745 r0 top
J3 "61300411121" WURTH_61300411121 820,115 r0 top
J4 "691101710002" Wurth_691101710002 2030,1725 r180 top
J5 "691101710002" Wurth_691101710002 2649.02,1395.39 r90 top
J6 "691101710002" Wurth_691101710002 2650,501.57 r90 top
J7 "61300821121" 61300821121 1188,820 r270 top
J8 "694106301002" Wurth_694106301002 1373.67,1486.82 r0 top
J9 "61300411121" WURTH_61300411121 2331.9,942.5 r270 top
J10 "61300311121" WURTH_61300311121 821,1444 r0 top
J11 "61300211121" WURTH_61300211121 1368,812 r270 top
LBL1 "THT-14-423-10" Label_650x200 2015,170 r0 top
LBL2 "THT-38-423-10" Label_375x375 835,945 r180 bottom
Logo1 "Texas Instruments" TI_Symbol_Overlay_Small 2490,140 r0 top
Logo2 "CE Mark" CE_Mark_5mm 1265,1760 r180 bottom
Logo3 "FCC disclaimer" FCC_disclaimer 773.08,198 r180 bottom
Logo4 "WEEE logo" WEEE_Minimum 1960,430 r180 bottom
LOGO5 "CAUTION HOT SURFACE" IEC_HotSurface_Small 2085,1360 r0 top
LOGO6 "CAUTION HOT SURFACE" IEC_HotSurface_Small 1126,1265.01 r180 bottom
LOGO7 "CAUTION HOT SURFACE" IEC_HotSurface_Small 1915,1510 r180 bottom
R1 "ERJ-3GEY0R00V" 0603L 295,1705 r90 top value=0
R2 "RC0603JR-0710KL" 0603L 776,388.82 r270 top value=10k
R3 "RC0603JR-0710KL" 0603L 854,388.82 r270 top value=10k
R4 "RC0603JR-07330RL" 0603 1270,335 r0 top value=330
R5 "RC0603JR-0710KL" 0603L 778,275.43 r270 top value=10k
R6 "RC0603JR-0710KL" 0603L 856,274 r270 top value=10k
R7 "RC0603JR-07330RL" 0603 1269,430 r0 top value=330
R8 "ERJ-3GEY0R00V" 0603L 437,811.65 r180 top value=0
R9 "CRCW060347K0JNEA" 0603L 436,634.2 r0 top value=47k
R10 "RC0603JR-0710KL" 0603L 1519,512 r270 top value=10k
R11 "RC0603JR-0710KL" 0603L 1813,873.56 r90 top value=10k
R12 "RC0603JR-0710KL" 0603L 1812.78,378.44 r270 top value=10k
RP1 "3352T-1-503LF" Bourns_3352T 205.01,817.01 r90 top value=50k
RP2 "3352T-1-503LF" Bourns_3352T 219.38,259.54 r90 top value=50k
S1 "430481025816" FP-430481025816_SMT_SW_6MM2_6MM2-MFG 193.31,1325 r270 top
SH-J1 "60900213421" Wurth_60900213421 868,1456 r180 top
SH-J2 "60900213421" Wurth_60900213421 775,1746 r180 top
SH-J3 "60900213421" Wurth_60900213421 1190.52,978.78 r180 top
SH-J4 "60900213421" Wurth_60900213421 1190.52,874.18 r180 top
SH-J5 "60900213421" Wurth_60900213421 1367,813 r90 top
SH-J6 "60900213421" Wurth_60900213421 1190.52,665 r180 top
SH-J10 "60900213421" Wurth_60900213421 878,1224 r180 top
TP1 "Jumper_2p" Harwin_D3082-05 1385,130 r180 top
TP2 "5012" Keystone5012 2708.69,1717.85 r0 top
TP3 "5012" Keystone5012 2708.69,1050 r0 top
TP4 "5012" Keystone5012 2708.69,824.98 r0 top
TP5 "5012" Keystone5012 2708.69,150 r0 top
TP6 "5002" Keystone5002 1493.61,1060.52 r90 top
TP7 "5002" Keystone5002 1498.29,931.69 r90 top
TP8 "5002" Keystone5002 1498.29,800.53 r90 top
TP9 "5002" Keystone5002 1500.64,669.36 r90 top
TP10 "5011" Keystone5011 1678.42,1770.38 r0 top
TP11 "5010" Keystone5010 2399.69,1770.38 r0 top
TP12 "5013" Keystone5013 140,1790 r0 top
U1 "DRV8421ADFUR" 0-IPC_C 2025,495 r0 top
U2 "DRV8421ADGQR" DGQ0010A-MFG 2030,970 r0 top
U3 "MSP430G2955IDA38R" DA0038A_L 813,721 r0 top
U4 "TPS7B6933DBVR" DBV0005A_N 410,1640 r0 top
ZZ1 "These assemblies are ESD sensitive, ESD precautions shall be observed." AssemblyNote 371,-546 r0 top
ZZ2 "These assemblies must be clean and free from flux and all contaminants. Use of no clean flux is not acceptable." AssemblyNote 1266,-363 r0 top
ZZ3 "These assemblies must comply with workmanship standards IPC-A-610 Class 2, unless otherwise specified." AssemblyNote 1140,-515 r0 top
ZZ4 "This Assembly Note is for PCB labels only" AssemblyNoteLabel 1261,-659 r0 top

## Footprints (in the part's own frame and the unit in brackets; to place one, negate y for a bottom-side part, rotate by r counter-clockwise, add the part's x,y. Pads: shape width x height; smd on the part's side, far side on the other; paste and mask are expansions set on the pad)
0-IPC_C [mm]
  rrect21% 1.874x0.486 smd paste+0 mask+0: 1(-2.316,2)
  rrect100% 1.874x0.486 smd paste+0 mask+0: 2(-2.316,1) 3(-2.316,0) 4(-2.316,-1) 5(-2.316,-2) 6(2.316,-2) 7(2.316,-1) 8(2.316,0) 9(2.316,1) 10(2.316,2)
  silkscreen extent -3.93,-2.45 0.88,2.45, body extent -3.35,-2.55 3.35,2.55, height 0.25
0603 [mm] "0603 from SM-752 data"
  rect 1x0.95 smd: 1(-0.8,0) 2(0.8,0)
  silkscreen extent -1.52,-0.69 1.52,0.69, body extent -0.87,-0.47 0.87,0.47, height 1
0603L [mm] "0603 from SM-752 data"
  rect 0.8x0.85 smd: 1(-0.7,0) 2(0.7,0)
  silkscreen extent -0.07,-0.32 0.07,0.32, body extent -0.87,-0.47 0.87,0.47, height 1
61300821121 [mm] "Pin Header, pitch 2.54 mm, THT, Vertical, dual row, 8p"
  rrect50% 1.65x1.65 hole 1.1: 1(-3.81,-1.27)
  round 1.65 hole 1.1: 2(-3.81,1.27) 3(-1.27,-1.27) 4(-1.27,1.27) 5(1.27,-1.27) 6(1.27,1.27) 7(3.81,-1.27) 8(3.81,1.27)
  silkscreen extent -5.23,-2.62 5.23,2.62, body extent -5.08,-2.54 5.08,2.54, height 8.59
AssemblyNote [mil] "Assembly Note"
AssemblyNoteLabel [mil] "Assembly Note for PCB Labels"
Bourns_3352T [mm] "TH, 3-Leads, Body 9.53x8.89mm, Pitch 2.54mm"
  rect 1.35x1.35 hole 0.85: 1(-2.54,0)
  round 1.35 hole 0.85: 2(0,0) 3(2.54,0)
  silkscreen extent -4.44,-2.6 4.44,7.31, body extent -4.44,-2.21 4.45,7.32, height 3.81
Bumpon_SJ61A1 [mil] "3M Cylindrical Bumpon black"
  round 1 on Mech4: 0(0,0)
  silkscreen extent -156,-156 156,156, body extent -156,-156 156,156, height 201
CE_Mark_5mm [mil] "Minimum text height for CE Mark"
  silkscreen extent -138,-98 138,98
DA0038A_L [mm] "TSOP, 38-Leads, Body 12.6x6.2mm (max), Pitch 0.65mm, IPC High Density"
  oval 1.2x0.4 smd: 1(-3.7,5.85) 2(-3.7,5.2) 3(-3.7,4.55) 4(-3.7,3.9) 5(-3.7,3.25) 6(-3.7,2.6) 7(-3.7,1.95) 8(-3.7,1.3) 9(-3.7,0.65) 10(-3.7,0) 11(-3.7,-0.65) 12(-3.7,-1.3) 13(-3.7,-1.95) 14(-3.7,-2.6) 15(-3.7,-3.25) 16(-3.7,-3.9) 17(-3.7,-4.55) 18(-3.7,-5.2) 19(-3.7,-5.85) 20(3.7,-5.85) 21(3.7,-5.2) 22(3.7,-4.55) 23(3.7,-3.9) 24(3.7,-3.25) 25(3.7,-2.6) 26(3.7,-1.95) 27(3.7,-1.3) 28(3.7,-0.65) 29(3.7,0) 30(3.7,0.65) 31(3.7,1.3) 32(3.7,1.95) 33(3.7,2.6) 34(3.7,3.25) 35(3.7,3.9) 36(3.7,4.55) 37(3.7,5.2) 38(3.7,5.85)
  silkscreen extent -4.23,-6.3 2.55,6.45, body extent -4.06,-6.25 4.06,6.25, height 1.2
DBV0005A_N [mm] "SOT23, 5-Leads, Body 2.9x1.6mm, Pitch 0.95mm, Lead Span 2.8mm, IPC Medium Density"
  rrect17% 1x0.6 smd: 1(-1.375,0.95) 2(-1.375,0) 3(-1.375,-0.95) 4(1.375,-0.95) 5(1.375,0.95)
  silkscreen extent -1.63,-1.55 0.38,1.55, body extent -1.42,-1.46 1.42,1.46, height 1.09
DGQ0010A-MFG [mm]
  rrect33% 1.45x0.3 smd paste+0 mask+0: 1(-2.2,1) 2(-2.2,0.5) 3(-2.2,0) 4(-2.2,-0.5) 5(-2.2,-1) 6(2.2,-1) 7(2.2,-0.5) 8(2.2,0) 9(2.2,0.5) 10(2.2,1)
  rrect5% 2.2x3.1 smd paste-1000 mask-1000: 11(0,0)
  silkscreen extent -3.6,-1.92 1.55,1.92, body extent -3.03,-1.8 3.03,1.8, height 0.25
FCC_disclaimer [mil]
Fiducial10-30 [mm]
  round 1 smd mask+1: 1(0,0)
  Top Layer keep-out circle w1.678: c0,0 r0.75
FP-430481025816_SMT_SW_6MM2_6MM2-MFG [mm]
  rrect7% 2x1.4 smd paste+0 mask+0: 1(-3.5,2) 2(3.5,2) 3(-3.5,-2) 4(3.5,-2)
  silkscreen extent -5.17,-3.2 3.2,3.2, body extent -4.6,-3.3 4.6,3.3, height 0.25
FP-885012006044_0603-MFG [mm]
  rrect13% 0.8x0.8 smd paste+0 mask+0: 1(-0.75,0) 2(0.75,0)
  silkscreen extent -0.85,-0.77 0.85,0.77, body extent -1.25,-0.55 1.25,0.55, height 0.25
FP-885012106031_0603-MFG [mm]
  rrect13% 0.8x0.8 smd paste+0 mask+0: 1(-0.75,0) 2(0.75,0)
  silkscreen extent -0.9,-0.77 0.9,0.77, body extent -1.25,-0.6 1.25,0.6, height 0.25
FP-GRM188R61E475KE15D_0603-MFG [mm]
  rrect13% 0.75x0.9 smd paste+0 mask+0: 1(-0.775,0) 2(0.775,0)
  silkscreen extent -0.9,-0.9 0.9,0.9, body extent -1.25,-0.6 1.25,0.6, height 0.25
Harwin_D3082-05 [mm] "Shorting Plug, 10.16mm spacing, TH"
  round 1.8 hole 1.3: 1(-5.08,0) 2(5.08,0)
  silkscreen extent -3.9,-0.53 3.9,0.53, body extent -5.6,-0.52 5.61,0.52, height 6.63
IEC_HotSurface_Small [mil]
  silkscreen extent -107,-93 107,92
Keystone5002 [mil] "For Keystone 500x miniature loop terminals"
  round 80 hole 40: 1(0,0)
  silkscreen extent -52,-52 52,52, body extent -49,-49 49,49, height 182
Keystone5010 [mil] "Keystone Multipurpose loops"
  round 87 hole 63: 1(0,0)
  silkscreen extent -70,-70 70,70, body extent -63,-63 63,62, height 319
Keystone5011 [mil] "Keystone Multipurpose loops"
  round 87 hole 63: 1(0,0)
  silkscreen extent -70,-70 70,70, body extent -63,-63 63,62, height 319
Keystone5012 [mil] "Keystone Multipurpose loops"
  round 87 hole 63: 1(0,0)
  silkscreen extent -70,-70 70,70, body extent -63,-63 63,62, height 319
Keystone5013 [mil] "Keystone Multipurpose loops"
  round 87 hole 63: 1(0,0)
  silkscreen extent -70,-70 70,70, body extent -63,-63 63,62, height 319
Label_375x375 [mil] "Thermal Transfer Label"
  round 1 on Mech14: 0(0,0)
  silkscreen extent -188,-188 188,188, body extent -188,-188 188,188, height 1
Label_650x200 [mil] "Thermal Transfer Label"
  round 1 on Mech13: 0(0,0)
  silkscreen extent -325,-100 325,100, body extent -325,-100 325,100, height 1
TI_Symbol_Overlay_Small [mil]
  silkscreen extent -90,-88 91,88
WCAP-ASLI_D6.3H5.5 [mm] "Aluminium Electrolytic V-Chip SMT Capacitors, 6.3x5.5mm"
  rect 3.5x1.6 smd: 1(2.8,0) 2(-2.8,0)
  silkscreen extent -3.4,-3.4 3.4,3.4, body extent -3.65,-3.3 3.65,3.3, height 5.5
WEEE_Minimum [mil] "WEEElie bin"
  silkscreen extent -95,-172 99,104
WL-SMCW_GREEN [mm] "WURTH"
  rect 0.8x0.8 smd: 1(-0.8,0) 2(0.8,0)
  silkscreen extent -1.9,-0.8 1.2,0.8, body extent -0.85,-0.45 0.85,0.45, height 0.8
WL-SMCW_RED [mm] "WURTH"
  rect 0.8x0.8 smd: 1(-0.8,0) 2(0.8,0)
  silkscreen extent -1.9,-0.8 1.2,0.8, body extent -0.85,-0.45 0.85,0.45, height 0.8
Wurth_60900213421 [mil] "Shunt, 2.54mm, Black"
  round 1 on Mech3: 0(0,0)
  body extent -98,-48 98,48, height 338
WURTH_61300211121 [mm] "Header, 2.54mm, 2x1, TH"
  rrect50% 1.65x1.65 hole 1.15: 1(-1.27,0)
  round 1.65 hole 1.15: 2(1.27,0)
  body extent -2.54,-1.27 2.54,1.27, height 8.54
WURTH_61300311121 [mm] "Header, 2.54mm, 3x1, TH"
  rrect50% 1.65x1.65 hole 1.15: 1(-2.54,0)
  round 1.65 hole 1.15: 2(0,0) 3(2.54,0)
  body extent -3.81,-1.27 3.81,1.27, height 8.54
WURTH_61300411121 [mm] "Header, 2.54mm, 4x1, TH"
  rrect50% 1.65x1.65 hole 1.15: 1(-3.81,0)
  round 1.65 hole 1.15: 2(-1.27,0) 3(1.27,0) 4(3.81,0)
  body extent -5.08,-1.27 5.08,1.27, height 8.54
Wurth_691101710002 [mm] "Terminal Block, 5 mm, 2x1, TH"
  rect 1.8x1.8 hole 1.3: 1(-2.5,0)
  round 1.8 hole 1.3: 2(2.5,0)
  silkscreen extent -5,-4.5 5.6,5, body extent -5.6,-4 5.6,5, height 12.5
Wurth_694106301002 [mm] "WR-DC DC Power Jack, R/A, TH"
  rect 3.5x1.3 hole 0.8 slot 3 at 0 deg: 1(0,-2.9) 2(0,2.9)
  rect 1.3x3.5 hole 0.8 slot 3 at 90 deg: 3(-4.8,0.1)
  silkscreen extent -4.5,-4.1 4.5,10.7, body extent -4.9,-3.8 4.5,10.7, height 10.63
